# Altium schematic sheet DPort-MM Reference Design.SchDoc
size A4; CheckedBy: AIoT事业部; Author: 工控机; CompanyName: 致远电子; SheetNumber: 01; SheetTotal: 1; PageSetup: Record=PageOptions¦CenterHorizontal=True¦CenterVertical=True¦PrintScale=1.00¦XCorrection=1.00¦YCorrection=1.00¦PrintKind=0¦BorderSize=5000000¦LeftOffset=0¦BottomOffset=0¦Orientation=2¦PaperLength=1000¦PaperWidth=1000¦Scale=100¦PaperSource=7¦PrintQuality=600¦MediaType=1¦DitherType=10¦PaperKind=A4¦PrintScaleMode=1; DesignDate: 2023/12/22; CheckDate: 2023/12/22; SheetName: DPort-MM Reference Design; SheetVersion: V1.0; SheetDescription: DPort-MM Reference Design; ProductName: 集成式透传模块; ProductModel: DPort-MM
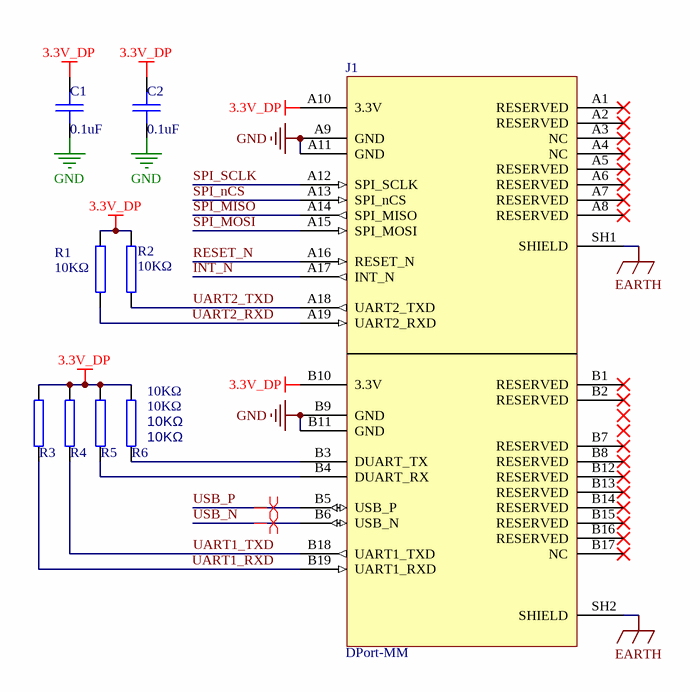
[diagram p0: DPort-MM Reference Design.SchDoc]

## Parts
C1  0.1uF  [0402C]
C2  0.1uF  [0402C]
J1  DPort-MM  [DPORT-G]
R1  10KΩ  [0402R]
R2  10KΩ  [0402R]
R3  10KΩ  [0402R]
R4  10KΩ  [0402R]
R5  10KΩ  [0402R]
R6  10KΩ  [0402R]

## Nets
3.3V_DP: C1.1 C2.1 J1.A10(3.3V) J1.B10(3.3V) R1.1 R2.1 R3.1 R4.1 R5.1 R6.1
EARTH: J1.SH1(SHIELD) J1.SH2(SHIELD)
GND: C1.2 C2.2 J1.A9(GND) J1.A11(GND) J1.B9(GND) J1.B11(GND)
INT_N: J1.A17(INT_N)
RESET_N: J1.A16(RESET_N)
SPI_MISO: J1.A14(SPI_MISO)
SPI_MOSI: J1.A15(SPI_MOSI)
SPI_nCS: J1.A13(SPI_nCS)
SPI_SCLK: J1.A12(SPI_SCLK)
UART1_RXD: J1.B19(UART1_RXD) R3.2
UART1_TXD: J1.B18(UART1_TXD) R4.2
UART2_RXD: J1.A19(UART2_RXD) R1.2
UART2_TXD: J1.A18(UART2_TXD) R2.2
USB_N: J1.B6(USB_N)
USB_P: J1.B5(USB_P)
NetJ1_B3: J1.B3(DUART_TX) R6.2
NetJ1_B4: J1.B4(DUART_RX) R5.2

Not connected (* = marked no-connect by the designer): J1 A1(RESERVED)* A2(RESERVED)* A3(NC)* A4(NC)* A5(RESERVED)* A6(RESERVED)* A7(RESERVED)* A8(RESERVED)* B1(RESERVED)* B2(RESERVED)* B7(RESERVED)* B8(RESERVED)* B12(RESERVED)* B13(RESERVED)* B14(RESERVED)* B15(RESERVED)* B16(RESERVED)* B17(NC)*

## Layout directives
differential pair: USB_N, USB_P

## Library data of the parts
C1 C2 = 02.01.00559: CC0402KRX5R8BB104,0402,YAGEO,0.1uF,X5R,±10%,25V,; 名称: 电容; 封装: 0402; 贴片和直插: SMT; 环保状态: RoHS2.0; 器件优选方案: 通用物料; 生产单位: PCS; PCB备注: 210628YYJ
J1 = DPort-MM: 集成式透传模块
R1-R6 = 01.01.00001: RTT02103JTH,0402,RALEC,10KΩ,±5%,1/16W; 旧物料代码: 1.01.17.0006; 名称: 电阻; 封装: 0402; 贴片和直插: SMT; 环保状态: RoHS2.0; 器件优选方案: 通用物料; 生产单位: PCS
